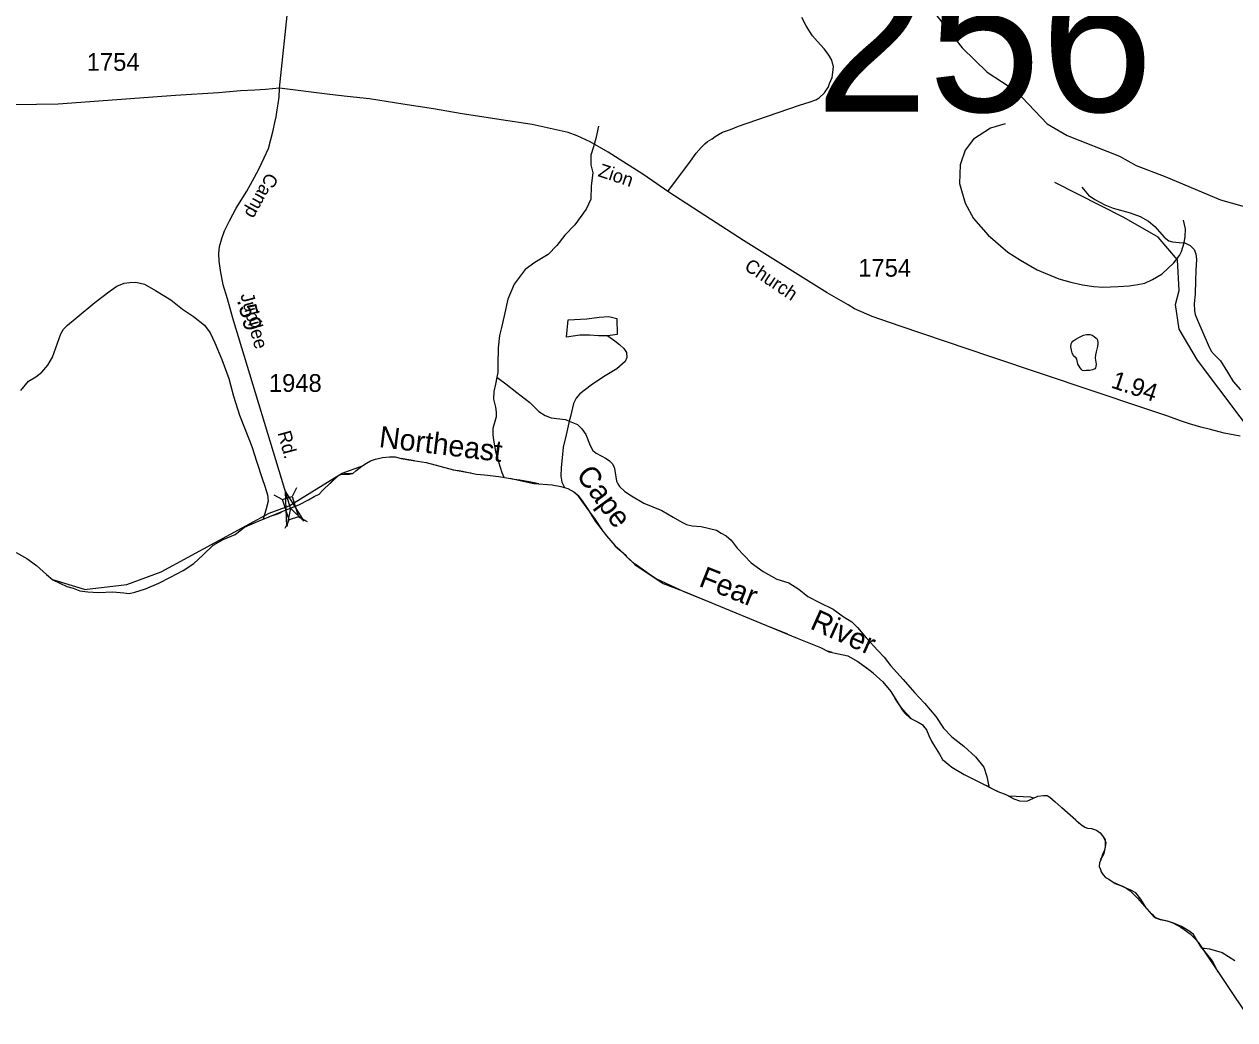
# Model space of a CAD drawing. Extents: x 2206922 to 2357709, y 510027 to 673830.
# Drawn here: x 2317208 to 2325732, y 515859 to 522867 of the extents above; entities that cross this region are included whole.
import ezdxf

# ---------------------------------------------------------------- set-up
doc = ezdxf.new("R2010")
doc.units = 0
for name, color, linetype in [('Exist Boundary Political CountyLine', 7, 'Continuous'), ('Exist Hydrographic Creek Single Shore Label', 7, 'Continuous'), ('Exist Hydrographic Misc Water Feature', 7, 'Continuous'), ('Exist Hydrographic Pond Under 1500 Sq Ft', 7, 'Continuous'), ('Exist Road Non-System Type 51', 7, 'Continuous'), ('Exist Road Secondary Mileage Hundredths English Label', 7, 'Continuous'), ('Exist Road Secondary Structure Standard Bridge Attributed CELL', 7, 'Continuous'), ('Exist Road Secondary Structure Standard Bridge CELL', 7, 'Continuous'), ('Exist Road Secondary Structure Standard Bridge Number Label', 7, 'Continuous'), ('Exist Road Secondary Type 51 Attributed', 7, 'Continuous'), ('Exist Road Secondary Type 51 Label', 7, 'Continuous'), ('Exist Road Secondary Type 51 Number Label', 7, 'Continuous')]:
    doc.layers.add(name, color=color, linetype=linetype)

msp = doc.modelspace()

# ---------------------------------------------------------------- linework, layer by layer
at = {"layer": 'Exist Boundary Political CountyLine'}
for points in [[(2317151.5, 519147.9), (2317225.9, 519106.8), (2317294.4, 519055.6), (2317365.2, 518992.2), (2317409.4, 518956.8), (2317507.9, 518910), (2317552.1, 518896.3), (2317600.2, 518878.9), (2317656.3, 518871.5), (2317730.3, 518866.3), (2317832.2, 518871.4), (2317910.3, 518864.2), (2317946.2, 518860.6), (2317988.1, 518869.1), (2318061.8, 518891.9), (2318155.4, 518932.8), (2318238.9, 518975.6), (2318328.4, 519022.6), (2318401.6, 519071.4), (2318467, 519132), (2318538.4, 519198.7), (2318609.9, 519239.6), (2318693.3, 519274.4), (2318758.8, 519327), (2318850.3, 519366.1), (2318989.7, 519421.6), (2319147, 519485.3), (2319210.6, 519519.9), (2319250.3, 519542.3), (2319286, 519558.7), (2319309.7, 519586.9), (2319361.2, 519635.4), (2319392.7, 519665.8), (2319410.7, 519682), (2319424.5, 519692.1), (2319436.5, 519698.2), (2319452.4, 519700.5), (2319496.4, 519698.8), (2319522.4, 519705.1), (2319544.1, 519723.4), (2319585.8, 519755.8), (2319617.6, 519776.1), (2319647.3, 519792.5), (2319681.2, 519804.7), (2319731.1, 519817.3), (2319779, 519821.8), (2319818.9, 519822.2), (2319863, 519810.8), (2319917.1, 519799.4), (2320037.3, 519780.6), (2320231.7, 519730.7), (2320335.9, 519711.8), (2320392.1, 519698.5), (2320450, 519695), (2320550.1, 519684.3), (2320658.2, 519663.4), (2320796.5, 519634.8), (2320924.6, 519624.3), (2320986.7, 519612.8), (2321036.8, 519599.5), (2321077, 519575.9), (2321109.2, 519550.4), (2321135.5, 519512.6), (2321176.2, 519453), (2321229.1, 519369.8), (2321308.1, 519266.5), (2321369, 519195.4)], [(2321369, 519195.4), (2321403.3, 519163.7), (2321451.7, 519118.3), (2321508.3, 519064.9), (2321608.9, 518996), (2321707.5, 518931.1), (2321854.1, 518872.6), (2322651.3, 518545.5), (2322815.8, 518479.3), (2322872.2, 518450), (2322940.2, 518434.7), (2323006.4, 518421.4), (2323076.8, 518380.2), (2323165.4, 518317.1), (2323254.2, 518238.1), (2323310.9, 518170.8), (2323351.7, 518101.2), (2323390.2, 518039.7), (2323408.5, 518017.9), (2323447, 517982.2), (2323503.1, 517954.9), (2323529.4, 517937.1), (2323561.7, 517899.6), (2323578.1, 517859.9), (2323596.5, 517820), (2323617, 517784.2), (2323651.6, 517728.6), (2323673.9, 517690.9), (2323738.5, 517637.7), (2323825, 517586.6), (2323967.7, 517514.1), (2324062.1, 517465.3), (2324120.4, 517443.8), (2324176.6, 517414.5), (2324216.8, 517400.9), (2324266.7, 517397.5), (2324308.6, 517415.8), (2324344.2, 517434.2), (2324384.4, 517436.7), (2324410.4, 517436.9), (2324430.4, 517425.1), (2324466.7, 517393.6), (2324614.1, 517261.3), (2324638.1, 517243.4), (2324644.3, 517235.7), (2324658.5, 517225.7), (2324676.4, 517216), (2324694.6, 517208.1), (2324722.6, 517204.4), (2324756.8, 517194.8), (2324782.9, 517175.1), (2324799.1, 517153.3), (2324811.4, 517135.4), (2324823.5, 517107.7), (2324819.9, 517077.5), (2324814.3, 517053.5), (2324802.5, 517029.4), (2324788.9, 516985.3), (2324779.1, 516963.3), (2324777.5, 516939.2), (2324785.8, 516917.3), (2324791.8, 516901.4), (2324804.1, 516879.5), (2324820.2, 516861.7), (2324844.3, 516847.9), (2324888.7, 516818.4), (2324938.7, 516799.1), (2324971, 516783.4), (2324995.3, 516767.5), (2325013.5, 516747.9), (2325047.6, 516716.2), (2325144.9, 516603.3), (2325157, 516591.4), (2325173.1, 516575.7), (2325205.1, 516565.9), (2325255.1, 516556.6), (2325295.4, 516541), (2325351.6, 516511.6), (2325375.9, 516493.8), (2325418.1, 516464.3), (2325454.7, 516426.8), (2325474.7, 516405), (2325840.4, 515859.2)]]:
    msp.add_lwpolyline(points, dxfattribs=at)
at = {"layer": 'Exist Hydrographic Misc Water Feature'}
for p, q in [((2320121.4, 519759), (2320112.5, 519761.2)), ((2322585, 518572.6), (2322461.4, 518623.3))]:
    msp.add_line(p, q, dxfattribs=at)
for points in [[(2321251.1, 522148.3), (2321232.2, 522062.1), (2321216.9, 522004), (2321197.4, 521945.8), (2321198.2, 521877.9), (2321212.8, 521820.1), (2321199.6, 521728), (2321196.8, 521636), (2321165.6, 521565.7), (2321084.6, 521454.9), (2321015.7, 521382.2), (2320958.5, 521309.6), (2320897.2, 521245), (2320803.7, 521190), (2320734.4, 521141.3), (2320657.5, 521036.5), (2320612.6, 520932), (2320588, 520813.9), (2320568.9, 520731.7), (2320553.5, 520675.6), (2320546.3, 520589.6), (2320543.7, 520469.6), (2320542.2, 520415.6), (2320534.6, 520381.5)], [(2324115.5, 522165.1), (2324011.9, 522134), (2323893, 522056.8), (2323833.7, 521980.2), (2323797, 521875.8), (2323794.2, 521745.9), (2323833.7, 521606.4), (2323892.8, 521499.1), (2323995.9, 521382.2), (2324133.3, 521261.8), (2324221.7, 521204.7), (2324340.4, 521138), (2324493, 521073.7), (2324577.2, 521050.6), (2324659.5, 521031.5), (2324739.4, 521020.4), (2324803.4, 521015.1), (2324909.4, 521020.2), (2324987.6, 521025), (2325049.3, 521033.7), (2325097.1, 521044.2), (2325152.8, 521068.8), (2325220.3, 521109.5), (2325303.5, 521186.4), (2325341.1, 521238.8), (2325356.4, 521266.9), (2325374.1, 521327)], [(2326068.8, 519703.1), (2325468.8, 520502.6), (2325340.7, 520720.6), (2325313.8, 520893.4), (2325338.8, 520992.9), (2325327.7, 521209.1), (2325192.8, 521367.7), (2324949.8, 521505.6), (2324463.6, 521751.8)], [(2324653.9, 521719.1), (2324702.7, 521663.6), (2324745, 521632.1), (2324817.2, 521594.9), (2324875.4, 521571.6), (2324995.8, 521538.9), (2325066.1, 521513.6), (2325124.5, 521480.3), (2325168.8, 521442.8), (2325233.4, 521367.5), (2325267.7, 521341.9), (2325293.9, 521334.2), (2325340, 521330.7), (2325374.1, 521327)], [(2325374.1, 521327), (2325374.1, 521331), (2325381.5, 521371.1), (2325384.7, 521427.1), (2325370.2, 521486.9)], [(2325374.1, 521327), (2325380, 521327.1), (2325418, 521309.6), (2325446.5, 521279.9), (2325456.7, 521250), (2325461.2, 521210), (2325456.1, 521132), (2325454.7, 521062.1), (2325451.8, 520966.1), (2325446.5, 520900.1), (2325447.1, 520848.1), (2325453.2, 520824.1), (2325469.8, 520782.4), (2325506.7, 520696.8), (2325543.5, 520609.2), (2325566, 520565.5), (2325586.3, 520541.7), (2325630.8, 520496.3), (2325679.6, 520416.8), (2325720.2, 520351.3), (2325772.7, 520293.9)], [(2317183.3, 520289.6), (2317238.6, 520354.1), (2317290.3, 520384.7), (2317331.9, 520417.1), (2317375.4, 520467.6), (2317406.8, 520523.8), (2317466.9, 520686.4), (2317484.7, 520720.6), (2317512.4, 520748.9), (2317581.7, 520805.6), (2317706.4, 520908.9), (2317813.6, 520990), (2317861.2, 521022.5), (2317910.8, 521045), (2317952.8, 521049.4), (2317994.9, 521049.9), (2318055, 521036.5), (2318133.3, 520991.4), (2318239.9, 520926.6), (2318322.5, 520861.5), (2318401.1, 520808.4), (2318478, 520747.2), (2318518.4, 520693.7), (2318551.2, 520624.1), (2318600.4, 520506.7), (2318649.6, 520373.3), (2318681.2, 520247.7), (2318724.4, 520114.2), (2318763.4, 520014.7), (2318810.6, 519895.3), (2318845.8, 519783.7), (2318883.2, 519668.2), (2318901.6, 519614.4), (2318920.5, 519554.7), (2318925, 519508.7), (2318911.5, 519454.6), (2318891.1, 519382.3)], [(2321317.1, 520673.8), (2321251.1, 520673.1), (2321189.2, 520678.4), (2321119.3, 520677.7), (2321027.4, 520664.7), (2321037.8, 520786.7), (2321169.9, 520792.2), (2321255.6, 520805.1), (2321323.7, 520809.8), (2321379.7, 520794.4), (2321382.9, 520682.5), (2321317.1, 520673.8)], [(2321317.1, 520673.8), (2321365.5, 520638.3), (2321399.8, 520612.7), (2321429.9, 520583.1), (2321448.2, 520555.3), (2321450.6, 520521.3), (2321438.9, 520493.2), (2321381.5, 520440.6), (2321286.2, 520383.6), (2321200.9, 520326.7), (2321119.7, 520263.9), (2321093.8, 520233.6), (2321076.4, 520197.5), (2321055.5, 520105.3), (2321045.6, 520073.2)], [(2324627.5, 520473.5), (2324619.1, 520509.4), (2324615, 520515.3), (2324595.1, 520533.1), (2324586.7, 520553), (2324582.6, 520573), (2324578.3, 520596.9), (2324579.9, 520616.9), (2324584, 520626.9), (2324591.8, 520635), (2324611.5, 520649.2), (2324637.5, 520663.5), (2324665.2, 520677.8), (2324687.2, 520682), (2324711.1, 520682.2), (2324727.1, 520678.5), (2324741.3, 520668.6), (2324755.4, 520656.8), (2324761.6, 520648.8), (2324765.7, 520640.9), (2324767.7, 520628.9), (2324767.7, 520618.9), (2324764.1, 520598.9), (2324754.4, 520560.8), (2324750.7, 520538.8), (2324749.1, 520516.8), (2324755.4, 520474.8), (2324753.6, 520456.8), (2324749.7, 520448.8), (2324745.8, 520440.7), (2324729.8, 520434.6), (2324708.1, 520430.3), (2324684.1, 520428.1), (2324672, 520428), (2324658, 520429.8), (2324653.9, 520433.8), (2324643.7, 520447.7), (2324635.7, 520459.6), (2324627.5, 520473.5)], [(2320534.6, 520381.5), (2320527.3, 520333.5), (2320513.7, 520281.4), (2320512.1, 520227.4), (2320526.9, 520171.6), (2320531.2, 520135.6), (2320531.6, 520103.6), (2320508.4, 520021.5), (2320507, 519979.5), (2320511.5, 519939.5), (2320526.2, 519859.7), (2320547, 519786), (2320569.9, 519712.2), (2320586.1, 519677.3)], [(2320534.6, 520381.5), (2320599.2, 520336.3), (2320677.6, 520275.1), (2320768.4, 520204.2), (2320831.2, 520140.9), (2320875.4, 520113.3), (2320919.3, 520095.8), (2321019.6, 520084.9), (2321045.6, 520073.2)], [(2321045.6, 520073.2), (2321043.6, 520061.2), (2321024.7, 519977), (2321003.6, 519888.8), (2320996.4, 519814.8), (2320989.2, 519746.7), (2320986, 519684.8), (2320994.4, 519642.9), (2321012.8, 519605.8)], [(2321045.6, 520073.2), (2321103.9, 520049.9), (2321134.2, 520018.2), (2321162.7, 519978.5), (2321193.5, 519900.8), (2321211.7, 519867.1), (2321235.9, 519847.4), (2321306.5, 519810.2), (2321328.4, 519794.4), (2321346.7, 519774.6), (2321361, 519748.7), (2321367.2, 519724.9), (2321378, 519651), (2321388.3, 519631.1), (2321398.5, 519613.3), (2321436.7, 519577.6), (2321483.2, 519546.2), (2321571.6, 519495.1), (2321698.1, 519444.6), (2321776.4, 519397.4), (2321839, 519362.1), (2321871, 519346.4), (2321911.2, 519336.9), (2321975.1, 519331.6), (2322081.4, 519304.7), (2322115.4, 519285.1), (2322149.6, 519265.5), (2322186.1, 519233.9), (2322228.8, 519178.4), (2322325.8, 519075.5), (2322410.3, 519014.4), (2322507, 518961.5), (2322591.1, 518934.4), (2322661.4, 518889.2), (2322726, 518837.9), (2322808.5, 518796.8), (2322903, 518749.8), (2322973.5, 518698.6), (2323035.7, 518659.3), (2323076.3, 518619.8), (2323137, 518546.5), (2323218, 518459.4), (2323262.5, 518411.9), (2323307, 518352.4), (2323395.9, 518255.4), (2323476.9, 518162.3), (2323547.7, 518087.1), (2323626.8, 517994), (2323679.5, 517912.6), (2323738.2, 517851.2), (2323822.7, 517784.2), (2323905.5, 517711.1), (2323964.1, 517637.8), (2323985.1, 517572.1), (2323999.9, 517500.7), (2324000.8, 517496.5)], [(2318933.6, 519425.5), (2319074.7, 519477.2), (2319424.3, 519692.2), (2319446.6, 519705.5), (2319589.8, 519758.9)], [(2319955.5, 519793.5), (2319917.1, 519799.5), (2319863, 519810.8)], [(2319522, 519702.5), (2319515.8, 519703.5), (2319496.1, 519701.5), (2319464.6, 519700.8), (2319453.2, 519697.5)], [(2320352, 519706.4), (2320335.4, 519709.6), (2320282.2, 519721.5), (2320231.3, 519727.7), (2320224.3, 519729.7)], [(2319394, 519663.8), (2319391.1, 519661.3), (2319361.5, 519634.9), (2319357.5, 519631.2)], [(2320830.4, 519632), (2320786.5, 519640.6), (2320698.5, 519657.7), (2320658, 519661.8), (2320628.8, 519668.1)], [(2321283.9, 519298), (2321226.9, 519387.5), (2321176.5, 519453.2), (2321164.6, 519468.6), (2321133.3, 519511.1), (2321112.3, 519543.3), (2321108, 519549.1), (2321084.7, 519569.7)], [(2317631.5, 518887.5), (2317930.7, 518922.5), (2318171.6, 519011), (2318933.6, 519425.5)], [(2319016.7, 519430), (2318990.6, 519418.8), (2318946.7, 519404.5), (2318933.3, 519399.1)], [(2321409.2, 519157.3), (2321402.8, 519163.2), (2321367.3, 519193.4)], [(2322045.3, 518793.8), (2321853.9, 518872.2), (2321829.9, 518882.2), (2321657.9, 518963.6), (2321608.8, 518995.9), (2321558.9, 519030.7), (2321508.7, 519065.6), (2321505.3, 519067.7), (2321451.7, 519118.3), (2321445.6, 519123.9), (2321409.2, 519157.3)], [(2317631.5, 518887.5), (2317410.1, 518956.2)], [(2322896.6, 518445.5), (2322872.7, 518451.5), (2322863.6, 518454.4)], [(2323185.5, 518299.1), (2323163.6, 518314.5), (2323116.5, 518350.1)], [(2323455.9, 517977.8), (2323392.3, 518045.5), (2323353, 518102.1), (2323340.9, 518119.4)], [(2323564.1, 517896.8), (2323562.7, 517900.6), (2323540.6, 517924)], [(2324000.8, 517496.5), (2323999.9, 517500.7), (2323967.4, 517513.5)], [(2324062.2, 517465.5), (2324038.3, 517477.4), (2324000.8, 517496.5)], [(2324315.4, 517418.7), (2324293.7, 517426.4), (2324141, 517433)], [(2324657.2, 517224.2), (2324644.1, 517235.5), (2324636.8, 517241.8), (2324612, 517263.1), (2324513, 517352)], [(2324786.2, 516987), (2324792.7, 516997.4), (2324812.4, 517029.2), (2324817.4, 517052.8), (2324822.1, 517075.3), (2324821.5, 517107.6), (2324821.5, 517113.6), (2324821.3, 517125.3), (2324813.6, 517136.9), (2324801.6, 517155), (2324793.2, 517163.2), (2324787.8, 517168.5)], [(2325107.8, 516646.3), (2325069.8, 516708.2), (2325035.3, 516751.8), (2324994.9, 516773.3), (2324971.2, 516784), (2324938.5, 516798.6), (2324908.7, 516812), (2324889.5, 516820.2), (2324880.2, 516824)], [(2325500.1, 516363.5), (2325475, 516400.8), (2325472.9, 516403.9), (2325468.1, 516412.2), (2325440.3, 516460.3), (2325416.1, 516480), (2325355.8, 516515.3), (2325295.3, 516540.6), (2325279.6, 516547.1), (2325254.4, 516553.5), (2325205.1, 516565.9), (2325174.8, 516577.5), (2325158.1, 516592.7), (2325145.6, 516604.1), (2325138.9, 516610.2)], [(2325500.1, 516363.5), (2325572, 516273.8), (2325613.1, 516196.1)], [(2325500.1, 516363.5), (2325517.2, 516363.1), (2325553.3, 516359.5), (2325643.5, 516332.5), (2325732.1, 516275.5)]]:
    msp.add_lwpolyline(points, dxfattribs=at)
at = {"layer": 'Exist Hydrographic Pond Under 1500 Sq Ft'}
msp.add_lwpolyline([(2323474.7, 523129.6), (2323812.8, 522700.2), (2323988.7, 522530.1), (2324190.7, 522397.1), (2324409.7, 522166.4), (2324551.8, 522083.5), (2324919.7, 521937.5), (2325036.8, 521873.3), (2325246.7, 521793.2), (2325630.8, 521631.5), (2325948.8, 521542.5)], dxfattribs=at)
at = {"layer": 'Exist Road Non-System Type 51'}
msp.add_lwpolyline([(2321739.1, 521689.3), (2321899.4, 521903.5), (2321939, 521959.9), (2321974.4, 521998.3), (2322000.2, 522024.6), (2322019.9, 522040.8), (2322051.7, 522061), (2322073.5, 522077.3), (2322097.4, 522089.5), (2322125.1, 522105.8), (2322180.9, 522126.5), (2322236.6, 522148.9), (2322366.2, 522194.3), (2322666.9, 522297.5), (2322742.6, 522320.3), (2322782.5, 522334.7), (2322806.3, 522349.1), (2322843.9, 522383.4), (2322871.4, 522425.7), (2322879.1, 522449.7), (2322896.8, 522492), (2322902.4, 522526), (2322905.9, 522568), (2322899.5, 522591.9), (2322893.4, 522613.9), (2322879.1, 522641.7), (2322862.8, 522663.4), (2322840.4, 522693.1), (2322794, 522744.7), (2322757.5, 522784.2), (2322733.1, 522824.1), (2322710.7, 522859.8), (2322682.3, 522913.4)], dxfattribs=at)
at = {"layer": 'Exist Road Secondary Structure Standard Bridge Attributed CELL'}
msp.add_lwpolyline([(2319056.7, 519332.2), (2319046.9, 519575.8), (2319177.2, 519369.7), (2319083.1, 519459.4)], close=True, dxfattribs=at)
at = {"layer": 'Exist Road Secondary Structure Standard Bridge CELL'}
for p, q in [((2319126, 519604.5), (2319094.3, 519543.2)), ((2318965.8, 519553.4), (2319027.1, 519521.7)), ((2319074.2, 519378.1), (2319042.5, 519316.8)), ((2319139.9, 519399.1), (2319201.2, 519367.4))]:
    msp.add_line(p, q, dxfattribs=at)
msp.add_lwpolyline([(2319094.3, 519543.2), (2319140.2, 519399.2), (2319073, 519377.8), (2319027.1, 519521.7)], close=True, dxfattribs=at)
at = {"layer": 'Exist Road Secondary Type 51 Attributed'}
for points in [[(2319006.5, 522416.1), (2319068.9, 523016.6), (2319137, 523726.2)], [(2319006.5, 522416.1), (2318906.3, 522406.5), (2318830.9, 522402.8), (2318731.9, 522396.6), (2318576.6, 522384.8), (2318273.4, 522363.8), (2317446.5, 522303.2), (2317141.3, 522298.1), (2316884.6, 522311.3), (2316706.8, 522327.8), (2316538.9, 522347.5), (2316380.9, 522377.2), (2315293, 522678.5), (2315049.4, 522751), (2314901.3, 522790.5), (2314766.3, 522820.1), (2314667.6, 522830), (2314531, 522828.4), (2314413.5, 522818.5), (2314323.5, 522813.5), (2314153.8, 522799.7), (2313598.3, 522760.7), (2312529.1, 522685.8)], [(2319083.1, 519459.4), (2318676.8, 520798.7), (2318639.7, 520933.7), (2318610, 521031.5), (2318590.2, 521133.1), (2318580.3, 521198.7), (2318579, 521251.9), (2318584, 521302.7), (2318600.1, 521358.4), (2318617.4, 521411.6), (2318653.3, 521483.5), (2318700.3, 521572.6), (2318775.8, 521691.5), (2318815.4, 521764.5), (2318860.6, 521846.9), (2318897.7, 521926.1), (2318927.4, 521993), (2318962, 522119.3), (2318973.2, 522173.7), (2318982.4, 522215.2), (2318989.3, 522262.9), (2318997.3, 522305.6), (2319002.2, 522352.7), (2319006.5, 522416.1)], [(2325770.3, 519966.2), (2325656, 519987), (2325559.5, 520013.8), (2325492.6, 520029.9), (2325413.4, 520054), (2325350.3, 520074.5), (2325261.2, 520107.9), (2325084.9, 520167.3), (2324013.9, 520525.8), (2323376.2, 520740.3), (2323177.6, 520809), (2323103.4, 520842.4), (2323055.1, 520862.9), (2323008.7, 520890.7), (2322927, 520939), (2322861, 520975.9), (2322273.6, 521343.9), (2321921, 521572.3), (2321739.1, 521689.3), (2321663, 521743.2), (2321564.6, 521811.9), (2321421.8, 521900.4), (2321319.5, 521966.1), (2321193.3, 522038.5), (2321102.4, 522081.2), (2321037.4, 522103.5), (2320783.6, 522160.1), (2320565.8, 522193.5), (2320277.5, 522238.1), (2320089.4, 522271.5), (2319874.1, 522305), (2319638.3, 522340.3), (2319481.2, 522357.6), (2319359.9, 522372.5), (2319006.5, 522416.1)]]:
    msp.add_lwpolyline(points, dxfattribs=at)

# ---------------------------------------------------------------- texts
at = {"layer": 'Exist Hydrographic Creek Single Shore Label'}
for s, rotation, p in [('Northeast', 353.03807, (2319701.3, 519890.7)), ('Cape', 306.28459, (2321088.7, 519693.4)), ('Fear', 338.363, (2321950.7, 518914.7)), ('River', 335.80846, (2322733.5, 518615.3))]:
    msp.add_text(s, height=150, rotation=rotation, dxfattribs=at).set_placement(p)
at = {"layer": 'Exist Road Secondary Mileage Hundredths English Label'}
for s, rotation, p in [('.59', 285.07908, (2318705, 520923.3)), ('1.94', 341.49588, (2324853.4, 520310.7))]:
    msp.add_text(s, height=125, rotation=rotation, dxfattribs=at).set_placement(p)
at = {"layer": 'Exist Road Secondary Structure Standard Bridge Number Label'}
msp.add_text('256', height=1066.27, dxfattribs=at).set_placement((2322779.2, 522251.4))
at = {"layer": 'Exist Road Secondary Type 51 Label'}
for s, rotation, p in [('Camp', 241.39093, (2318919.3, 521828.7)), ('Zion', 341.58124, (2321242.6, 521797.9)), ('Church', 326.13255, (2322271.9, 521144)), ('Jubilee', 285.13054, (2318729.6, 520961.7)), ('Rd.', 285.13054, (2318991.4, 519991))]:
    msp.add_text(s, height=95, rotation=rotation, dxfattribs=at).set_placement(p)
at = {"layer": 'Exist Road Secondary Type 51 Number Label'}
for s, p in [('1754', (2317648.4, 522538.6)), ('1754', (2323080.6, 521089.7)), ('1948', (2318931, 520278.8))]:
    msp.add_text(s, height=125, dxfattribs=at).set_placement(p)

doc.saveas('drawing.dxf')
